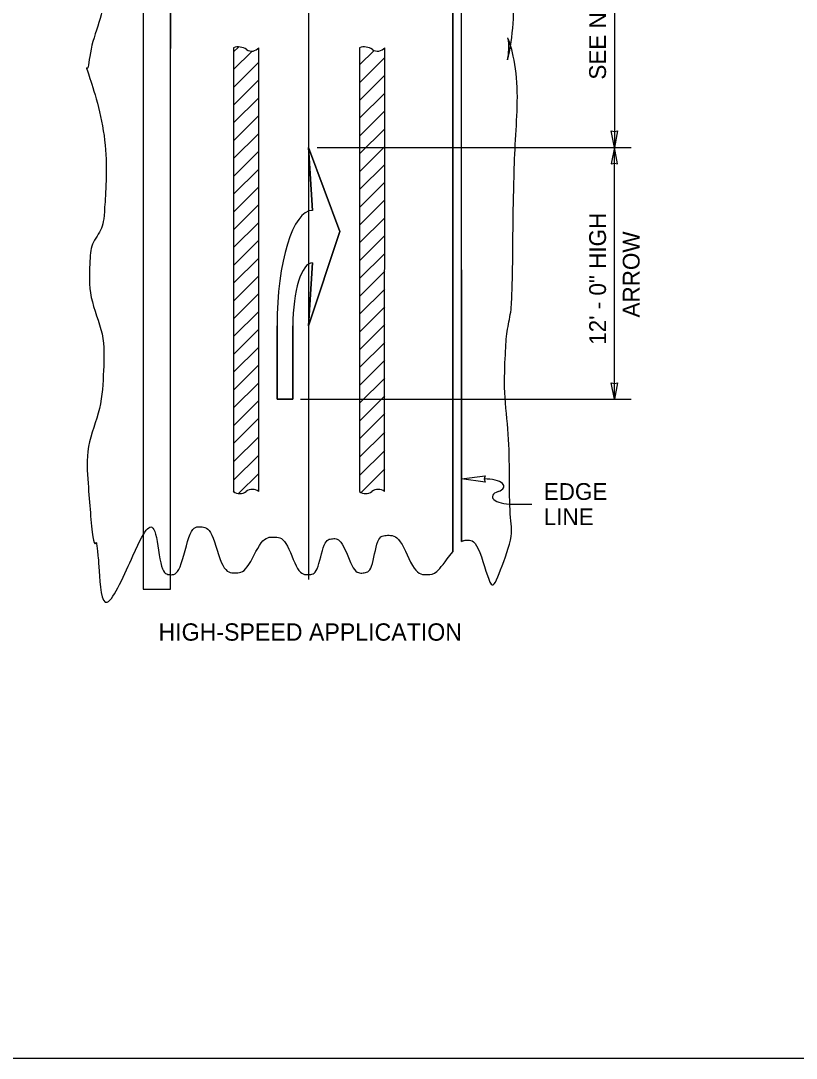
# Model space of a CAD drawing. Extents: x 99862 to 103151, y 100000 to 105076.
# Drawn here: x 100601 to 101341, y 100000 to 100988 of the extents above; entities that cross this region are included whole.
import ezdxf

# ---------------------------------------------------------------- set-up
doc = ezdxf.new("R2010")
doc.units = 0
for name, color, linetype in [('Level 1', 7, 'Continuous'), ('Level 15', 7, 'Continuous'), ('Level 2', 7, 'Continuous'), ('Level 20', 7, 'Continuous'), ('Level 5', 7, 'Continuous'), ('Level 6', 7, 'Continuous'), ('Level 7', 7, 'Continuous')]:
    doc.layers.add(name, color=color, linetype=linetype)

msp = doc.modelspace()

# ---------------------------------------------------------------- linework, layer by layer
at = {"layer": 'Level 1'}
msp.add_lwpolyline([(99862, 99999.5), (103151, 99999.5), (103151, 102075.5), (99862, 102075.5)], close=True, dxfattribs=at)
at = {"layer": 'Level 15'}
for p, q in [((100875.59, 101353.95), (100875.59, 100873.86)), ((101167.16, 101106.54), (101167.16, 100867.54)), ((100875.59, 100873.86), (100875.59, 100455.7)), ((100883.95, 100867.54), (101183.11, 100867.54)), ((101167.16, 100627.54), (101167.16, 100867.54)), ((100868.01, 100627.54), (101183.11, 100627.54)), ((101069.7, 100527.58), (101088.31, 100527.58))]:
    msp.add_line(p, q, dxfattribs=at)
for points in [[(101167.16, 100867.54), (101164.08, 100883.27), (101167.16, 100882.54), (101170.24, 100883.27)], [(101167.16, 100867.54), (101164.08, 100851.82), (101167.16, 100852.55), (101170.24, 100851.82)], [(101167.16, 100627.54), (101164.08, 100643.27), (101167.16, 100642.54), (101170.24, 100643.27)], [(101021.28, 100551.58), (101044.11, 100554.56), (101043.06, 100551.58), (101044.11, 100548.59)]]:
    msp.add_lwpolyline(points, close=True, dxfattribs=at)
for centre, radius, start, end in [((100808.66, 100949.85), 13.45, 54.48639, 109.2534), ((100821.41, 100967.96), 8.7, 235.40734, 321.53495), ((100928.66, 100949.85), 13.45, 54.48639, 109.2534), ((100941.41, 100967.96), 8.7, 235.40734, 321.53495), ((100810.07, 100547.63), 10, 233.1301, 306.8699), ((100822.07, 100531.63), 10, 53.1301, 126.8699), ((100930.07, 100547.63), 10, 233.1301, 306.8699), ((100942.07, 100531.63), 10, 53.1301, 126.8699)]:
    msp.add_arc(centre, radius, start, end, dxfattribs=at)
for centre, start_param, end_param in [((101043.06, 100544.55), 2.356226, 4.712389), ((101069.57, 100534.61), 5.497747, 7.861127)]:
    msp.add_ellipse(centre, major_axis=(-18.75, 0), ratio=0.375, start_param=start_param, end_param=end_param, dxfattribs=at)
at = {"layer": 'Level 2'}
msp.add_lwpolyline([(100743.87, 101613.33), (100717.88, 101613.33), (100717.88, 100446.41), (100743.87, 100446.41)], close=True, dxfattribs=at)
for points in [[(100879.34, 100757.54), (100875.59, 100697.54), (100905.59, 100787.54), (100875.59, 100867.54), (100879.34, 100807.54)], [(100845.59, 100697.54), (100845.59, 100627.54), (100860.59, 100627.54), (100860.59, 100697.54)]]:
    msp.add_lwpolyline(points, dxfattribs=at)
for major_axis, ratio in [((0, -110), 0.306818), ((0, -60), 0.3125)]:
    msp.add_ellipse((100879.34, 100697.54), major_axis=major_axis, ratio=ratio, start_param=3.141593, end_param=4.712389, dxfattribs=at)
at = {"layer": 'Level 5'}
for p, q in [((100879.34, 100807.54), (100875.59, 100867.54)), ((100875.59, 100867.54), (100905.59, 100787.54)), ((100905.59, 100787.54), (100875.59, 100697.54)), ((100875.59, 100697.54), (100879.34, 100757.54)), ((100845.59, 100627.54), (100845.59, 100697.54)), ((100860.59, 100697.54), (100860.59, 100627.54)), ((100860.59, 100627.54), (100845.59, 100627.54))]:
    msp.add_line(p, q, dxfattribs=at)
for major_axis, ratio in [((0, -110), 0.306818), ((0, -60), 0.3125)]:
    msp.add_ellipse((100879.34, 100697.54), major_axis=major_axis, ratio=ratio, start_param=3.141593, end_param=4.712389, dxfattribs=at)
at = {"layer": 'Level 6'}
for p, q in [((100804.23, 100958.71), (100808.72, 100963.2)), ((100804.23, 100941.74), (100821.89, 100959.4)), ((100924.23, 100946.17), (100938.04, 100959.99)), ((100924.23, 100929.2), (100948.23, 100953.2)), ((100804.23, 100924.77), (100828.23, 100948.77)), ((100804.23, 100907.8), (100828.23, 100931.8)), ((100924.23, 100912.23), (100948.23, 100936.23)), ((100804.23, 100890.83), (100828.23, 100914.83)), ((100924.23, 100895.26), (100948.23, 100919.26)), ((100924.23, 100878.29), (100948.23, 100902.29)), ((100804.23, 100873.85), (100828.23, 100897.85)), ((100804.23, 100856.88), (100828.23, 100880.88)), ((100924.23, 100861.32), (100948.23, 100885.32)), ((100804.23, 100839.91), (100828.23, 100863.91)), ((100924.23, 100844.35), (100948.23, 100868.35)), ((100924.23, 100827.38), (100948.23, 100851.38)), ((100804.23, 100822.94), (100828.23, 100846.94)), ((100924.23, 100810.41), (100948.23, 100834.41)), ((100804.23, 100805.97), (100828.23, 100829.97)), ((100804.23, 100789), (100828.23, 100813)), ((100924.23, 100793.44), (100948.23, 100817.44)), ((100804.23, 100772.03), (100828.23, 100796.03)), ((100924.23, 100776.47), (100948.23, 100800.47)), ((100924.23, 100759.49), (100948.23, 100783.49)), ((100804.23, 100755.06), (100828.23, 100779.06)), ((100804.23, 100738.09), (100828.23, 100762.09)), ((100924.23, 100742.52), (100948.23, 100766.52)), ((100804.23, 100721.12), (100828.23, 100745.12)), ((100924.23, 100725.55), (100948.23, 100749.55)), ((100924.23, 100708.58), (100948.23, 100732.58)), ((100804.23, 100704.15), (100828.23, 100728.15)), ((100924.23, 100691.61), (100948.23, 100715.61)), ((100804.23, 100687.18), (100828.23, 100711.18)), ((100804.23, 100670.21), (100828.23, 100694.21)), ((100924.23, 100674.64), (100948.23, 100698.64)), ((100804.23, 100653.24), (100828.23, 100677.24)), ((100924.23, 100657.67), (100948.23, 100681.67)), ((100924.23, 100640.7), (100948.23, 100664.7)), ((100804.23, 100636.27), (100828.23, 100660.27)), ((100804.23, 100619.3), (100828.23, 100643.3)), ((100924.23, 100623.73), (100948.23, 100647.73)), ((100804.23, 100602.33), (100828.23, 100626.33)), ((100924.23, 100606.76), (100948.23, 100630.76)), ((100924.23, 100589.79), (100948.23, 100613.79)), ((100804.23, 100585.36), (100828.23, 100609.36)), ((100924.23, 100572.29), (100948.23, 100596.29)), ((100804.23, 100567.86), (100828.23, 100591.86)), ((100804.23, 100550.36), (100828.23, 100574.36)), ((100924.23, 100554.79), (100948.23, 100578.79)), ((100808.94, 100537.57), (100828.23, 100556.86)), ((100925.71, 100538.77), (100948.23, 100561.29)), ((100803.89, 100539.45), (100804.75, 100540.31))]:
    msp.add_line(p, q, dxfattribs=at)
for points in [[(100717.88, 101613.33), (100717.88, 100476.27)], [(100717.88, 101613.33), (100717.88, 100961.85)], [(100743.87, 100475.4), (100743.87, 101613.33)], [(100743.87, 101613.33), (100743.87, 100961.85)], [(101013.08, 101585.87), (101013.08, 100482.15)], [(101020.94, 101570.38), (101020.94, 100491.97)], [(100804.23, 100962.55), (100804.07, 100539.63)], [(100828.07, 100539.63), (100828.23, 100962.55)], [(100924.23, 100962.55), (100924.07, 100539.63)], [(100948.07, 100539.63), (100948.23, 100962.55)]]:
    msp.add_lwpolyline(points, dxfattribs=at)
at = {"layer": 'Level 7'}
msp.add_line((101020.94, 101570.38), (101021.33, 100491.97), dxfattribs=at)
msp.add_lwpolyline([(101013.08, 100482.15), (101013.08, 101584.93)], dxfattribs=at)
for points in [[(100681.09, 101573.7), (100681.04, 101571.06), (100681, 101568.41), (100681, 101565.77), (100680.97, 101552.44), (100684.36, 101539.14), (100684.26, 101525.87), (100684.14, 101511.75), (100676.57, 101498.22), (100675.71, 101484.14), (100674.45, 101463.75), (100678.72, 101442.78), (100677.74, 101422.46), (100677.12, 101409.63), (100672.18, 101396.8), (100671.63, 101383.99), (100670.89, 101366.41), (100680.22, 101348.83), (100680.18, 101331.26), (100680.15, 101315.77), (100672.21, 101300.33), (100672.04, 101284.85), (100671.79, 101261.54), (100683.97, 101238.15), (100683.44, 101214.82), (100682.84, 101188.1), (100668.58, 101161.75), (100667.97, 101135.03), (100667.12, 101098.04), (100682.69, 101060.37), (100681, 101023.27), (100679.66, 100993.89), (100667.41, 100964.85), (100665.53, 100935.53), (100660.91, 100952.74), (100685.5, 100878.47), (100681, 100806.51), (100679.99, 100790.32), (100667.93, 100775.54), (100667.16, 100759.28), (100665.51, 100724.57), (100681.68, 100689.76), (100680.18, 100655.05), (100678.61, 100618.68), (100662.8, 100582.4), (100665.53, 100545.94), (100667.51, 100519.42), (100670.03, 100492.75), (100672.45, 100488.07), (100673.42, 100493.48), (100674.29, 100482.82), (100675.71, 100472.19), (100678.77, 100411.14), (100711.89, 100487.59), (100722.53, 100507.61), (100730.43, 100506.2), (100734.76, 100460.96), (100743.7, 100460.38), (100753.06, 100459.78), (100762.76, 100506.89), (100773.01, 100505.98), (100783.36, 100505.07), (100793.49, 100462.14), (100805.58, 100462.01), (100816.72, 100461.9), (100830.79, 100496.36), (100842.63, 100496.21), (100854.06, 100496.07), (100865.28, 100460.29), (100875.61, 100460.38), (100884.32, 100460.46), (100890.05, 100493.91), (100898.41, 100494.58), (100907.31, 100495.3), (100918.68, 100461.13), (100927.72, 100462.01), (100936.47, 100462.87), (100940.77, 100497.63), (100950.52, 100497.84), (100962.95, 100498.1), (100976.25, 100460.22), (100989.6, 100460.38), (100997.33, 100460.48), (101005.21, 100472.16), (101013.08, 100482.15)], [(101021.33, 100491.97), (101022.74, 100492.71), (101024.15, 100493.17), (101025.56, 100493.24), (101037.19, 100493.88), (101049.58, 100441.96), (101055.69, 100457.42), (101071.31, 100496.91), (101067.3, 100514.72), (101067.09, 100554.58), (101066.88, 100594.2), (101061.44, 100633.92), (101063.43, 100673.46), (101064.36, 100692.11), (101069, 100710.55), (101069.53, 100729.24), (101070.44, 100761.04), (101070.43, 100792.89), (101071.16, 100824.71), (101072, 100861.16), (101074.47, 100897.61), (101075.23, 100934.02), (101067.99, 100968.38), (101064.09, 100974.46), (101067.62, 100965.18), (101063.4, 100941.34), (101071.15, 100976.83), (101071.16, 101012.36), (101071.17, 101042.75), (101067.68, 101073.21), (101067.9, 101103.56), (101068.25, 101149.61), (101080.95, 101195.49), (101081.34, 101241.37), (101081.58, 101269.5), (101071.92, 101297.53), (101071.16, 101325.65), (101070.16, 101362.83), (101080.29, 101400.43), (101079.3, 101437.61), (101078.85, 101454.54), (101071.44, 101471.14), (101071.16, 101488.09), (101070.96, 101500.3), (101075.92, 101512.51), (101074.82, 101524.73), (101074.01, 101533.83), (101073.2, 101542.92), (101072.38, 101552.01)]]:
    msp.add_open_spline(points, degree=3, dxfattribs=at)

# ---------------------------------------------------------------- texts
at = {"layer": 'Level 20'}
for s, rotation, p in [('SEE NOTE', 90, (101159.16, 100932.11)), ('12\' - 0" HIGH ', 90, (101159.16, 100679.43)), ('ARROW', 90, (101191.16, 100705.43)), ('EDGE ', 360, (101099.81, 100531.58)), ('LINE', 360, (101099.81, 100507.58))]:
    msp.add_text(s, height=16, rotation=rotation, dxfattribs=at).set_placement(p)
msp.add_text('HIGH-SPEED APPLICATION', height=16.5, dxfattribs=at).set_placement((100732.54, 100397.45))

doc.saveas('drawing.dxf')
